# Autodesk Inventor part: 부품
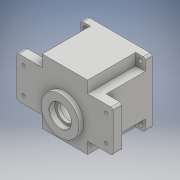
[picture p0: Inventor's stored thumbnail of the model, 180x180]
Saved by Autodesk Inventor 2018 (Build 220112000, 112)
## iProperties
Created: 2020-07
Part Number: 부품
Material: 일반
Document SubType Name: Modeling
Designer: Admin
Density: 1 g/cm^3
Appearance: 기본값
Author: Admin
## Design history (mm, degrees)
sketch "스케치1"
  geometry: L1 (0, -65.8)-(0, 65.8) reference; L2 (-98, 0)-(98, 0) reference; L3 (33, 47)-(-33, 47); L4 (-33, 47)-(-33, 30); L5 (-33, 30)-(-70, 30); L6 (-70, 30)-(-70, -30); L7 (-70, -30)-(-33, -30); L8 (-33, -30)-(-33, -47); L9 (-33, -47)-(33, -47); L10 (33, -47)-(33, -30); L11 (33, -30)-(70, -30); L12 (70, -30)-(70, 30); L13 (70, 30)-(33, 30); L14 (33, 47)-(33, 30); 1 further point
  constraints: 24 end point, 8 perpendicular, 7 point on line, 1 horizontal, 3 other
  dimensions: "d0" = 140 distance between parallel lines of L6 L12; "d1" = 60 distance between parallel lines of L7 L5; "d2" = 66 distance of L3.start L3.end; "d3" = 17 distance of L3.end L4.end; "d4" = 17 distance of L7.end L8.end
extrude "돌출1" new body sketch "스케치1" distance "d5" = 13; taper "d6" = 0 deg
sketch "스케치2"
  geometry: L1 (-33, -47)-(33, -47) reference; L2 (33, -47)-(33, -30) reference; L3 (33, -30)-(70, -30) reference; L4 (70, -30)-(70, 30) reference; L5 (70, 30)-(33, 30) reference; L6 (33, 30)-(33, 47) reference; L7 (33, 47)-(-33, 47) reference; L8 (-33, 47)-(-33, 30) reference; L9 (-33, 30)-(-70, 30) reference; L10 (-70, 30)-(-70, -30) reference; L11 (-70, -30)-(-33, -30) reference; L12 (-33, -30)-(-33, -47) reference; L13 (-47, -47)-(47, -47); L14 (47, -47)-(47, 47); L15 (47, 47)-(-47, 47); L16 (-47, 47)-(-47, -47); L17 (-47, -47)-(47, 47); L18 (47, -47)-(-47, 47); 1 further point
  constraints: 12 end point, 2 midpoint, 2 parallel, 1 horizontal, 1 perpendicular
  dimensions: "d7" = 94 distance of L14.end L15.end; "d8" = 94 distance of L13.end L14.end
extrude "돌출2" join sketch "스케치2" distance "d9" = 67; taper "d10" = 0 deg
sketch "스케치3"
  geometry: L1 (-33, 47)-(33, 47) reference; L2 (-33, 30)-(-33, 47) reference; L3 (-70, 30)-(-33, 30) reference; L4 (-70, -30)-(-70, 30) reference; L5 (-33, -30)-(-70, -30) reference; L6 (-33, -47)-(-33, -30) reference; L7 (33, -47)-(-33, -47) reference; L8 (33, -30)-(33, -47) reference; L9 (70, -30)-(33, -30) reference; L10 (70, 30)-(70, -30) reference; L11 (33, 30)-(70, 30) reference; L12 (33, 47)-(33, 30) reference; L13 (33, 47)-(47, 47) reference; L14 (47, 47)-(47, 30) reference; L15 (47, -30)-(47, -47) reference; L16 (47, -47)-(33, -47) reference; L17 (-33, -47)-(-47, -47) reference; L18 (-47, -47)-(-47, -30) reference; L19 (-47, 30)-(-47, 47) reference; L20 (-47, 47)-(-33, 47) reference; L21 (47, -47)-(-47, -47) reference; L22 (-47, -47)-(-33, -47); L23 (-33, -47)-(-33, -30); L24 (-33, -30)-(-47, -30); L25 (-47, -30)-(-47, -47); L26 (-47, 30)-(-33, 30) reference; L27 (-47, 30)-(-33, 30); L28 (-33, 30)-(-33, 47); L29 (-33, 47)-(-47, 47); L30 (-47, 47)-(-47, 30); L31 (33, 47)-(33, 30) reference; L32 (33, 30)-(47, 30); L33 (47, 30)-(47, 47); L34 (47, 47)-(33, 47); L35 (33, 47)-(33, 30); L36 (33, -47)-(-33, -47) reference; L37 (33, -47)-(47, -47); L38 (47, -47)-(47, -30); L39 (47, -30)-(33, -30); L40 (33, -30)-(33, -47); 1 further point
  constraints: 32 end point, 8 parallel, 4 horizontal, 4 perpendicular
extrude "돌출3" cut sketch "스케치3" distance "d11" = 70; taper "d12" = 0 deg
sketch "스케치8"
  geometry: L1 (98, 0)-(-98, 0) reference; L2 (0, 65.8)-(0, -65.8) reference; C1 r 43 at (0, 0); 1 further point
  constraints: 1 centre point, 1 coincident
  dimensions: "d28" = 86 diameter of C1
extrude "돌출8" cut sketch "스케치8" distance "d29" = 9; taper "d30" = 0 deg
sketch "스케치9"
  geometry: C1 r 43 at (0, 0) reference; C2 r 40 at (0, 0); 1 further point
  constraints: 1 centre point, 1 coincident
  dimensions: "d31" = 80 diameter of C2
extrude "돌출9" cut sketch "스케치9" distance "d32" = 55; taper "d33" = 0 deg
sketch "스케치13"
  geometry: L1 (0, 65.8)-(0, -65.8) reference; L2 (98, 0)-(-98, 0) reference; L3 (-35.778, 3.994)-(-39.8, 3.994); L4 (-35.778, -3.994)-(-39.8, -3.994); C1 r 40 at (0, 0) reference; C2 r 43 at (0, 0) reference; A1 r 40 centre (0, 0) between (-39.8, 3.994) and (-39.8, -3.994) reference; A2 r 36 centre (0, 0) between (-36, 0) and (-35.778, 3.994); A3 r 4 centre (-36, 0) between (-36.222, -3.994) and (-36.222, 3.994); A4 r 40 centre (0, 0) between (-39.8, 3.994) and (-39.8, -3.994); 1 further point
  constraints: 11 point on circle, 4 end point, 3 centre point, 3 point on line, 2 coincident, 2 horizontal
  dimensions: "d45" = 72 diameter of A2; "d46" = 8 diameter of A3
extrude "돌출13" join sketch "스케치13" stored distance "d47" = 7; taper "d48" = 0 deg
sketch "스케치14"
  geometry: L1 (0, 65.8)-(0, -65.8) reference; L2 (98, 0)-(-98, 0) reference; L3 (-35.778, 3.994)-(-39.8, 3.994) reference; L4 (-39.8, -3.994)-(-35.778, -3.994) reference; C1 r 43 at (0, 0) reference; A1 r 40 centre (0, 0) between (-39.8, -3.994) and (-39.8, 3.994) reference; A2 r 4 centre (-36, 0) between (-35.778, -3.994) and (-35.778, 3.994) reference; 2 further points
  constraints: 1 coincident
hole "구멍1" sketch "스케치14" at (-36, 0) diameter "d49" = 3.242; stored, may be unused: countersink angle "d53" = 90 deg, drill point angle "d55" = 118 deg; dims "d50" = 7, "d51" = 4, "d52" = 2, "d54" = 9
sketch "스케치24"
  geometry: L1 (0, 65.8)-(0, -65.8) reference; L2 (98, 0)-(-98, 0) reference; L3 (70, -30)-(70, 30) reference; C1 r 5 at (60, -19); C2 r 5 at (60, 19); C3 r 5 at (-60, -19); C4 r 5 at (-60, 19); 5 further points
  constraints: 4 centre point, 4 symmetric about line, 2 coincident, 2 other
  dimensions: "d67" = 38 distance of point (60, -19) point (60, 19); "d68" = 10 distance from line of L3 point (60, -19); "d69" = 10 distance from line of L3 point (60, 19); "d70" = 19 distance from line of L2 point (60, -19); "d71" = 10 diameter of C1; "d72" = 10 diameter of C2
extrude "돌출17" cut sketch "스케치24" distance "d73" = 5; taper "d74" = 0 deg
sketch "스케치25"
  geometry: L1 (60, 84.8)-(60, -46.8) reference; C1 r 5 at (120, 0) reference; C2 r 5 at (120, 38) reference; C3 r 5 at (0, 38) reference; C4 r 5 at (0, 0) reference; C5 r 2.25 at (120, 0); C6 r 2.25 at (120, 38); C7 r 2.25 at (0, 0); C8 r 2.25 at (0, 38); 1 further point
  constraints: 4 centre point, 2 coincident, 2 symmetric about line, 2 other
  dimensions: "d75" = 4.5 diameter of C5; "d76" = 4.5 diameter of C6
extrude "돌출18" cut sketch "스케치25" extent not by distance; stored distance "d77" = 0; taper "d78" = 0 deg
sketch "스케치26"
  geometry: L1 (-98, 0)-(98, 0) reference; L2 (0, 65.8)-(0, -65.8) reference; L3 (-47, 47)-(47, 47) reference; L4 (47, 47)-(47, -47) reference; L5 (47, -47)-(-47, -47) reference; L6 (-47, -47)-(-47, 47) reference; L7 (40, -40)-(-40, -40); L8 (-40, -40)-(-40, 40); L9 (-40, 40)-(40, 40); L10 (40, 40)-(40, -40); L11 (40, -40)-(-40, 40); L12 (-40, -40)-(40, 40); C1 r 43 at (0, 0) reference; C2 r 3.5 at (40, -40); C3 r 3.5 at (40, 40); C4 r 3.5 at (-40, -40); C5 r 3.5 at (-40, 40); 1 further point
  constraints: 12 end point, 4 centre point, 3 symmetric about line, 2 midpoint, 2 parallel, 1 coincident, 1 horizontal, 1 perpendicular, 3 other
  dimensions: "d79" = 80 distance of L7.end L8.end; "d80" = 80 distance of L8.end L9.end; "d81" = 7 diameter of C2
extrude "돌출19" cut sketch "스케치26" extent not by distance; stored distance "d82" = 5; taper "d83" = 0 deg
sketch "스케치27"
  geometry: L1 (-14, 80)-(80, 80) reference; 2 further points
  constraints: 1 other
  dimensions: "d84" = 40 distance from line of L1 point (32.773, 40)
feature "엠보싱1" sketch "스케치27" dims "d0" = 140, "d1" = 60, "d2" = 66, "d3" = 17, "d4" = 17, "d85" = 0.5, "d86" = 0
fillet "모깎기1" dims "d87" = 3
chamfer "모따기1" distance "d89" = 1; stored, may be unused: second distance "d90" = 2, angle "d91" = 45 deg
sketch "스케치28"
  geometry: L1 (35.778, 3.994)-(39.8, 3.994) reference; L2 (-39.8, 3.994)-(-35.778, 3.994) reference; L3 (-35.778, -3.994)-(-39.8, -3.994) reference; L4 (39.8, -3.994)-(35.778, -3.994) reference; L5 (0, 65.8)-(0, -65.8) reference; L6 (98, 0)-(-98, 0) reference; C1 r 11 at (0, -20); A1 r 40 centre (0, 0) between (39.8, 3.994) and (-39.8, 3.994) reference; A2 r 4 centre (-36, 0) between (-35.778, -3.994) and (-35.778, 3.994) reference; A3 r 40 centre (0, 0) between (-39.8, -3.994) and (39.8, -3.994) reference; A4 r 4 centre (36, 0) between (35.778, 3.994) and (35.778, -3.994) reference; 1 further point
  constraints: 1 centre point, 1 point on line
  dimensions: "d98" = 22 diameter of C1; "d99" = 20 distance from line of C1.centre L6
extrude "돌출20" cut sketch "스케치28" distance "d100" = 7; taper "d101" = 0 deg
sketch "스케치29"
  geometry: L1 (0, 65.8)-(0, -65.8) reference; L2 (-98, 0)-(98, 0) reference; C1 r 27.5 at (0, -11); 1 further point
  constraints: 1 centre point, 1 point on line
  dimensions: "d104" = 55 diameter of C1; "d105" = 11 distance from line of L2 C1.centre
extrude "돌출21" join sketch "스케치29" distance "d106" = 7; taper "d107" = 0 deg
sketch "스케치30"
  geometry: C1 r 11 at (0, 0) reference; C2 r 9.5 at (0, 0); 1 further point
  constraints: 1 centre point, 1 coincident
  dimensions: "d108" = 19 diameter of C2
extrude "돌출22" cut sketch "스케치30" distance "d109" = 3; taper "d110" = 0 deg
sketch "스케치32"
  geometry: C1 r 27.5 at (0, 0) reference; C2 r 16 at (0, 0); 1 further point
  constraints: 1 centre point, 1 coincident
  dimensions: "d111" = 32 diameter of C2
extrude "돌출23" cut sketch "스케치32" distance "d112" = 8.3; taper "d113" = 0 deg
sketch "스케치33"
  geometry: C1 r 16 at (0, 0) reference; C2 r 12.5 at (0, 0); 1 further point
  constraints: 1 centre point, 1 coincident
  dimensions: "d114" = 25 diameter of C2
extrude "돌출24" cut sketch "스케치33" distance "d115" = 4.7; taper "d116" = 0 deg
sketch "스케치34"
  geometry: C1 r 12.5 at (0, 0) reference; C2 r 17.5 at (0, 0); 1 further point
  constraints: 1 centre point, 1 coincident
  dimensions: "d117" = 35 diameter of C2
extrude "돌출25" cut sketch "스케치34" distance "d118" = 10; taper "d119" = 0 deg
chamfer "모따기4" distance "d120" = 0.8; stored, may be unused: second distance "d121" = 2, angle "d122" = 30 deg
fillet "모깎기3" dims "d126" = 3
sketch "스케치36"
  geometry: L1 (35.778, 3.994)-(39.8, 3.994) reference; L2 (-39.8, 3.994)-(-35.778, 3.994) reference; L3 (-35.778, -3.994)-(-39.8, -3.994) reference; L4 (39.8, -3.994)-(35.778, -3.994) reference; C1 r 17.5 at (0, 11) reference; C2 r 11 at (0, -20) reference; A1 r 40 centre (0, 0) between (39.8, 3.994) and (-39.8, 3.994) reference; A2 r 4 centre (-36, 0) between (-35.778, -3.994) and (-35.778, 3.994) reference; A3 r 40 centre (0, 0) between (-39.8, -3.994) and (39.8, -3.994) reference; A4 r 4 centre (36, 0) between (35.778, 3.994) and (35.778, -3.994) reference; A5 r 21 centre (0, 11) between (8.978, -7.984) and (-8.978, -7.984); A6 r 15 centre (0, -20) between (-8.978, -7.984) and (8.978, -7.984); 1 further point
  constraints: 4 point on circle, 2 centre point, 2 coincident
  dimensions: "d129" = 42 diameter of A5; "d130" = 30 diameter of A6
extrude "돌출26" join sketch "스케치36" distance "d131" = 7; taper "d132" = 0 deg
chamfer "모따기6" distance "d133" = 1; stored, may be unused: second distance "d134" = 2, angle "d135" = 45 deg
node "솔리드1"
mirror "미러1"
node "투영된 루프1"
node "투영된 루프2"
node "투영된 루프10"
node "투영된 루프11"
node "투영된 루프15"
node "투영된 루프16"
node "투영된 루프17"
node "투영된 루프19"
node "투영된 루프20"
node "투영된 루프21"
node "투영된 루프23"
other parameters: "d127" = 42
